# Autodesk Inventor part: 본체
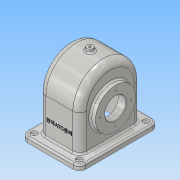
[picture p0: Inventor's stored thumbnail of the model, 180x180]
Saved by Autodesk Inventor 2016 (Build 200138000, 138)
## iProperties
Created: 2018-08
Part Number: 본체
Material: 알루미늄 6061
Document SubType Name: Modeling
Designer: Administrator
Density: 2.7 g/cm^3
Appearance: 알루미늄 - 평지
Mass: 1092.15 g
Surface Area: 1182.13 cm^2
Volume: 404.501 cm^3
Author: Administrator
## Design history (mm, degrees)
sketch "스케치1"
  geometry: L1 (-55, 75)-(55, 75); L2 (55, 75)-(55, -75); L3 (55, -75)-(-55, -75); L4 (-55, -75)-(-55, 75); L5 (-55, 75)-(55, -75); L6 (55, 75)-(-55, -75); 1 further point
  constraints: 12 end point, 2 midpoint, 2 parallel, 1 horizontal, 1 perpendicular
  dimensions: "d0" = 150 distance of L1.end L2.end; "d1" = 110 distance of L1.start L1.end
extrude "돌출1" new body sketch "스케치1" distance "d2" = 10; taper "d3" = 0 deg
sketch "스케치2"
  geometry: L1 (-58, 78)-(-58, 10); L2 (58, 78)-(58, 10); L3 (75, 0)-(-75, 0) reference; L4 (-75, 10)-(75, 10) reference; A1 r 58 centre (0, 78) between (58, 78) and (-58, 78); 2 further points
  constraints: 4 end point, 2 point on circle, 2 point on line, 2 tangent, 2 vertical, 1 centre point, 1 midpoint, 1 vertical alignment
  dimensions: "d4" = 58 radius of A1; "d5" = 78 distance from line of L1.start L3
extrude "돌출2" join sketch "스케치2" stored distance "d6" = 77; taper "d7" = 0 deg
sketch "스케치3"
  geometry: L1 (-58, 10)-(-58, 78) reference; L2 (58, 78)-(58, 10) reference; L3 (-52, 0)-(-52, 78); L4 (52, 78)-(52, 0); L5 (-75, 0)-(75, 0) reference; L6 (-52, 0)-(52, 0); A1 r 58 centre (0, 78) between (58, 78) and (-58, 78) reference; A2 r 52 centre (0, 78) between (52, 78) and (-52, 78); 1 further point
  constraints: 6 end point, 2 point on circle, 2 point on line, 1 centre point, 1 collinear, 2 other
  dimensions: "d14" = 6 radial gap between concentric circles of A1 A2
extrude "돌출3" cut sketch "스케치3" stored distance "d15" = 67; taper "d16" = 0 deg
sketch "스케치4"
  geometry: L1 (-38.5, 65)-(38.5, 65); L2 (38.5, 78)-(38.5, 10) reference; L3 (-33.5, 0)-(33.5, 0) reference; L4 (43.5, 65)-(43.5, 103); L5 (33.5, 104.747)-(19.5, 93); L6 (19.5, 93)-(19.5, 65); L7 (43.5, 65)-(19.5, 65); L8 (38.5, 78)-(38.5, 136) reference; L9 (33.5, 78)-(33.5, 130) reference; L10 (-38.5, 65)-(-48.5, 65); L11 (-48.5, 65)-(-48.5, 103); L12 (-48.5, 103)-(-38.5, 103); L13 (-38.5, 103)-(-38.5, 65); L14 (-38.5, 136)-(-38.5, 78) reference; L15 (43.5, 103)-(33.5, 103); L16 (33.5, 103)-(33.5, 104.747); 1 further point
  constraints: 22 end point, 5 point on line, 3 horizontal, 3 perpendicular, 2 parallel, 2 vertical
  dimensions: "d17" = 65 distance between parallel lines of L3 L1; "d19" = 5 distance between parallel lines of L8 L4; "d20" = 24 distance between parallel lines of L4 L6; "d23" = 76 diameter of L12 L1; "d24" = 87 distance between parallel lines of L11 L8; "d35" = 56 diameter of L5.end L1; "d36" = 50 deg angle of L6 L5; "d37" = 76 diameter of L15 L1
revolve "회전1" sketch "스케치4" stored, may be unused: angle "d25" = 90 deg
hole "구멍1" diameter "d28" = 40; stored, may be unused: countersink angle "d32" = 90 deg, drill point angle "d34" = 118 deg; dims "d26" = 10, "d27" = 10, "d29" = 6, "d30" = 4, "d31" = 2, "d33" = 8
node "작업 평면1"
sketch "스케치6"
  geometry: L1 (0, 142)-(0, 135); L2 (-6.612, 135)-(-6, 142); L3 (-6, 142)-(0, 142); L4 (38.5, 136)-(-38.5, 136) reference; L5 (-33.5, 0)-(33.5, 0) reference; L6 (0, 135)-(-6.612, 135); 1 further point
  constraints: 8 end point, 1 horizontal, 1 point on line, 1 vertical
  dimensions: "d43" = 95 deg angle of L4 L2; "d44" = 12 diameter of L2.end L1; "d45" = 142 distance between parallel lines of L5 L3; "d47" = 1 distance between parallel lines of L4 L6
revolve "회전2" sketch "스케치6" stored, may be unused: angle "d46" = 90 deg
hole "구멍2" diameter "d50" = 4.134; stored, may be unused: countersink angle "d54" = 90 deg, drill point angle "d56" = 118 deg; dims "d48" = 10, "d49" = 10, "d51" = 10, "d52" = 4, "d53" = 2, "d55" = 8
sketch "스케치7"
  geometry: L1 (0, 0)-(29, 0); C1 r 20 at (0, 0) reference; 1 further point
  constraints: 2 end point, 1 horizontal
  dimensions: "d57" = 29 distance of L1.start L1.end
hole "구멍3" sketch "스케치7" at (29, 0) diameter "d58" = 3.242; stored, may be unused: countersink angle "d62" = 90 deg, drill point angle "d64" = 118 deg; dims "d59" = 8, "d60" = 4, "d61" = 2, "d63" = 10
sketch "스케치8"
  geometry: L1 (0, 0)-(-29, 0); C1 r 20 at (0, 0) reference; 1 further point
  constraints: 2 end point, 1 horizontal
  dimensions: "d68" = 29 distance of L1.start L1.end
hole "구멍4" sketch "스케치8" at (-29, 0) diameter "d69" = 3.242; stored, may be unused: countersink angle "d73" = 90 deg, drill point angle "d75" = 118 deg; dims "d70" = 8, "d71" = 4, "d72" = 2, "d74" = 10
fillet "모깎기1" dims "d79" = 12
sketch "스케치9"
  geometry: A1 r 12 centre (43, -63) between (43, -75) and (55, -63) reference; A2 r 12 centre (43, 63) between (55, 63) and (43, 75) reference; A3 r 12 centre (-43, 63) between (-43, 75) and (-55, 63) reference; A4 r 12 centre (-43, -63) between (-55, -63) and (-43, -75) reference; 5 further points
  constraints: 4 coincident
hole "구멍5" sketch "스케치9" at (43, -63), (43, 63), (-43, 63), (-43, -63) diameter "d80" = 5; stored, may be unused: countersink angle "d84" = 90 deg, drill point angle "d86" = 118 deg; dims "d81" = 5, "d82" = 12, "d83" = 4, "d85" = 5
fillet "모깎기2" dims "d87" = 13
fillet "모깎기3" dims "d88" = 8
fillet "모깎기4" dims "d89" = 3
chamfer "모따기1" distance "d90" = 1; stored, may be unused: second distance "d91" = 2, angle "d92" = 45 deg
sketch "스케치10"
  geometry: L1 (-13, 0)-(-13, -65) reference; L2 (68.5, -78)-(-17.5, -78) reference; 2 further points
  constraints: 1 other
  dimensions: "d93" = 38.5 distance from line of point (25.5, -38) L1; "d94" = 40 distance from line of L2 point (25.5, -38)
feature "엠보싱1" sketch "스케치10" dims "d0" = 150, "d1" = 110, "d95" = 0.5, "d96" = 0
node "작업 평면2"
sketch "스케치11"
  geometry: L1 (133.951, 153.638)-(-112.75, 153.638); L2 (-112.75, 153.638)-(-112.75, -19.549); L3 (-112.75, -19.549)-(133.951, -19.549); L4 (133.951, -19.549)-(133.951, 153.638); 1 further point
  constraints: 8 end point, 2 parallel, 1 horizontal, 1 perpendicular
extrude "돌출5" cut sketch "스케치11" stored distance "d97" = 10; taper "d98" = 0 deg
node "솔리드1"
pattern_circular "원형 패턴1" dims angle "d66" = 360 deg
pattern_circular "원형 패턴2" dims angle "d77" = 360 deg
other parameters: "d38" = 142
